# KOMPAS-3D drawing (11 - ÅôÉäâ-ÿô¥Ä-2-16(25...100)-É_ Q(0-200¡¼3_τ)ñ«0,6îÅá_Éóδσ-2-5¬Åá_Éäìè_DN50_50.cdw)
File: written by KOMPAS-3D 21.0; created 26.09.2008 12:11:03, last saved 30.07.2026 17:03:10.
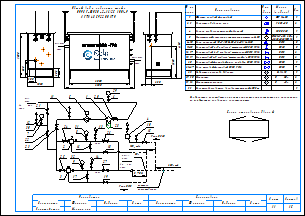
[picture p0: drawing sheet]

Sheets 1-2: A3, landscape

Document properties: Наименование: Макро:21; Автор: RaskoAdmin; Форматы листов документа: 2xA3; Полное имя файла: \\UR38nt01\Departments\КТО\КБ ПУРДГ\Заявки\Прайс-лист на типовые шкафы ГРПШ\ПУРДГ_стандарт_30_04_2026\ПУРДГ с РДНК\ПУРДГ-ШУЭО-2-16(25...100)-Р_ Q(0-200нм3_ч)до0,6МПа_Рвых-2-5кПа_РДНК_DN50_50.cdw

Title block, sheet 1: Наименование: Пункт учета газа / ПУГ-Ш-400-Р / ЛГТИ.485922.001ТУ; designation: ЛГТИ.03.4411141; sheet number: 1; Количество листов документа: 2; organisation: ООО "ЭЛЬСТЕР Газэлектроника"; Форматы листов документа: A3; stored path: C:\Рабочие документы\Компас\ПУГ\Схема.cdw; Разработал: Устинов; Проверил: Кошкин; Утвердил: Кошкин
Title block, sheet 2: sheet number: 2; stored path: D:\Рабочие документы\Заявки\ПУРДГ\ПУРДГ-ШУЭО-2-100-Р 4411220.cdw; designation, second copy: ЛГТИ.03.4411141-

Views: Вид 1, Вид 2
Referenced files: wcvoit.frw
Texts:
  Normal
  № на
  схеме
  Усл.
  обозн.
  Марка
  (модель)
  Кол.
  Фильтр газовый фланцевый
  ФГ 16-50
  Регулятор давления газа
  РДНК-50
  Клапан предохранительный сбросной
  КПС DN20
  Измерительный комплекс с ротационным счетчиком Ду50
  СГ-ЭК-Р-(0,2...2,0)-
  Кран кнопочный VE-РАСКО-НЗ-1,6-G1/2-М20
  DN15
  Кран шаровой "под приварку" штуцерный DN20 PN16
  DN20
  Кран шаровой "под приварку" штуцерный DN15 PN16
  Кран шаровой "под приварку" штуцерный п/п DN15 PN16
  Кран шаровой фланцевый с мех. приводом DN50 PN16
  Кран шаровой фланцевый DN50 PN16
  DN50
  Индикатор перепада давления
  Манометр
  Манометр-напоромер
  Электрообогреватель взрывозащищенный 400Вт
  Delta 15
  0...     МПа
  0...     кПа
  Общий вид и габариты шкафа
  ПУРДГ-ШУЭО-2-16(25...100)-Р
  Выход газа
  Вход газа
  logo-rasko-ge.png
  DN 1
  местное
  сопротивление
  Римп DN15
  Римп DN20
  Выход
  газа
  Р=     кПа
  Вход
  Р=       МПа
  PDI
  Схема открывания дверей
  Предприятие изготовитель может заменять комплектующие на аналогичные,
  не ухудшающие заявленных характеристик.
  Должность
  Конструктор
  Фамилия
  Подпись
  Дата
  Согласовано
  Максимкин
  Лист
  Листов
  POLYLINE_STYLE_0.18_RGB_0_0_0
  POLYLINE_STYLE_0.50_RGB_0_0_0
  POLYLINE_STYLE_0.34_RGB_0_0_0
  PHANTOM_RGB_0_0_0_SC_1_THICK_0.18
  K5LT_THIN_RGB_0_0_0_THICK_0.18
  K5LT32769_RGB_0_0_0_THICK_0.18
  K5LT12_RGB_0_0_0_SC_1_THICK_0.18
  K5LT_DASHED_RGB_0_0_0_SC_1_THICK_0.18
  ACISOTGL_RGB_0_0_0_SC_0.8_THICK_0.25
  CONTINUOUS_RGB_0_127_31_THICK_0.3
  CONTINUOUS_RGB_0_0_255_THICK_0.35
  CONTINUOUS_RGB_255_0_0_THICK_0.35
  POLYLINE_STYLE_0.25_RGB_0_0_0
  CONTINUOUS_RGB_0_0_0_THICK_0.5
  POLYLINE_STYLE_0.35_RGB_0_0_255
  CONTINUOUS_RGB_0_0_0_THICK_0.4
  CONTINUOUS_RGB_0_0_0_THICK_0.35
  НЕВИДИМАЯ_RGB_0_0_0_SC_0.3_THICK_0.25
  СONTINUOUS_RGB_0_0_0_THICK_0.25
  ОСЕВАЯ2_RGB_248_153_30_SC_0.3_THICK_0.25
  Без оформления
Dimensions and other numbers on the sheet: 1; 2, 3; 2; 4; 5; 6-10; 11-15; 16, 17; 18, 19; 20; 21-27; 7; 28; 29, 30; 31, 32; 33; 1500; 250; 300; 1050; 550; 305; 2000; 4130; 2300; 5,,,7DN 1; 30; 12; 21; 22; 23; 11; 6; 29; 24; 31; 8; 16; 13; 26; 18; 10; 15; 25; 32; 9; 3; 17; 14; 27; 19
